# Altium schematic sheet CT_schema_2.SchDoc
size 313 x 185 mm
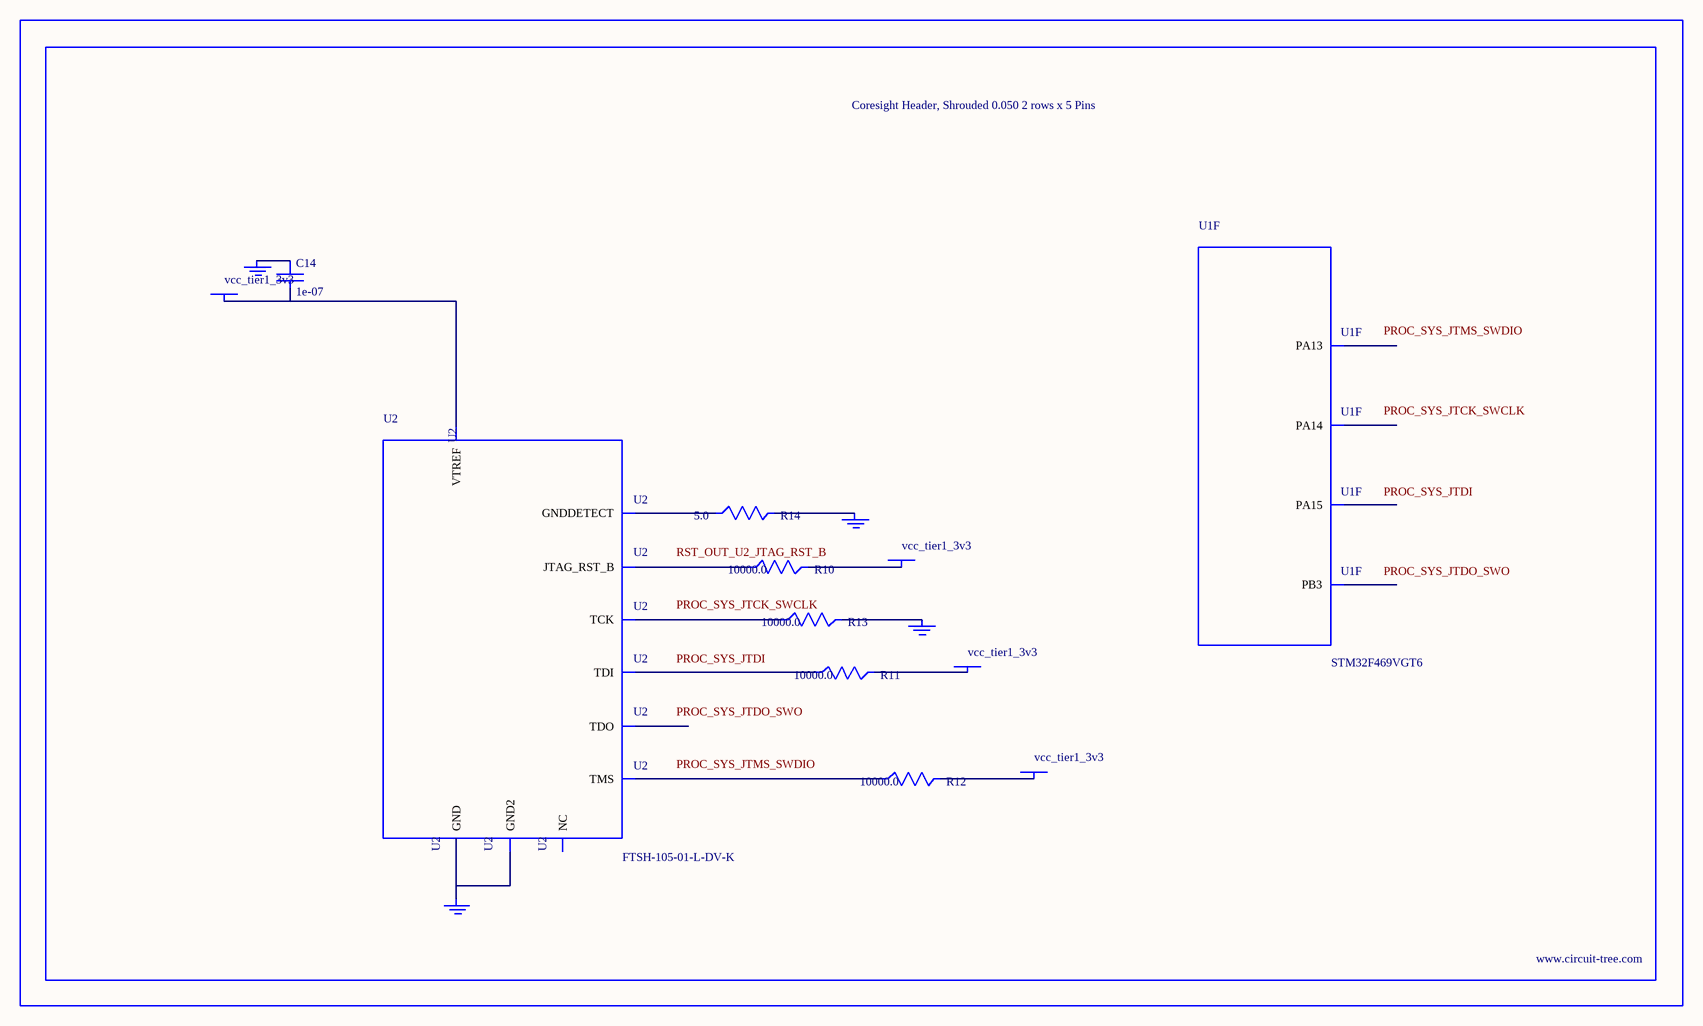
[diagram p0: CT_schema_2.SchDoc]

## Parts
BORDER1  (no value)
C14  1e-07  [C0402]
GND_INSTANCE_1_0  (no value)
GND_INSTANCE_1_1  (no value)
GND_INSTANCE_1_2  (no value)
GND_INSTANCE_1_3  (no value)
POWER_INSTANCE_1_0  vcc_tier1_3v3
POWER_INSTANCE_1_1  vcc_tier1_3v3
POWER_INSTANCE_1_2  vcc_tier1_3v3
POWER_INSTANCE_1_3  vcc_tier1_3v3
R10  10000.0  [R0603]
R11  10000.0  [R0603]
R12  10000.0  [R0603]
R13  10000.0  [R0603]
R14  5.0  [R0603]
U1  STM32F469VGT6  [LQFP100]  (part F of 10)
U2  FTSH-105-01-L-DV-K  [SAMTEC_FTSH-105-01-L-DV-K]

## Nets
NetC14_1: C14.1 GND_INSTANCE_1_0.0(GND)
NetC14_2: C14.2 POWER_INSTANCE_1_0.0(PWR) U2.1(VTREF)
NetGND_INSTANCE_1_1_0: GND_INSTANCE_1_1.0(GND) R13.2
NetGND_INSTANCE_1_2_0: GND_INSTANCE_1_2.0(GND) R14.2
NetGND_INSTANCE_1_3_0: GND_INSTANCE_1_3.0(GND) U2.3(GND) U2.5(GND2)
NetPOWER_INSTANCE_1_1_0: POWER_INSTANCE_1_1.0(PWR) R12.2
NetPOWER_INSTANCE_1_2_0: POWER_INSTANCE_1_2.0(PWR) R11.2
NetPOWER_INSTANCE_1_3_0: POWER_INSTANCE_1_3.0(PWR) R10.2
NetR10_1: R10.1 U2.10(JTAG_RST_B)
NetR11_1: R11.1 U2.8(TDI)
NetR12_1: R12.1 U2.2(TMS)
NetR13_1: R13.1 U2.4(TCK)
NetR14_1: R14.1 U2.9(GNDDETECT)

Not connected (* = marked no-connect by the designer): U1 75(PA13) 79(PA14) 80(PA15) 92(PB3); U2 6(TDO) 7(NC)

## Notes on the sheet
- Labels drawn without touching a wire or pin: PROC_SYS_JTCK_SWCLK, PROC_SYS_JTDI, PROC_SYS_JTDO_SWO, PROC_SYS_JTMS_SWDIO, RST_OUT_U2_JTAG_RST_B

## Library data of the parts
BORDER1 = BORDER_PAGE1
C14 = C0402C104K3RACTU
GND_INSTANCE_1_0-GND_INSTANCE_1_3 = GND
POWER_INSTANCE_1_0-POWER_INSTANCE_1_3 = PWR
R10-R13 = RC0603JR-0710KL
R14 = ERJ-3GEYJ5R1V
